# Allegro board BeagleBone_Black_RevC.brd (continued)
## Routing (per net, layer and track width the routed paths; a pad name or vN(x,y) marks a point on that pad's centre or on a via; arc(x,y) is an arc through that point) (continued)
DDR_DQM1: length 20.2
  TOP w0.121: U12.D3 61.5,28.76 60.01,28.76 59.44,28.19 57.78,28.19 57.66,28.32 57.66,28.57 57.78,28.7 59.31,28.7 59.44,28.83 59.44,29.08 59.31,29.21 57.78,29.21 57.66,29.34 57.66,29.59 57.78,29.72 59.31,29.72 59.44,29.84 59.44,30.1 59.31,30.23 56.77,30.23 56.64,30.1 56.64,29.34 56.52,29.21 52.12,29.21 U5.J2
DDR_DQS0: length 23.3
  TOP w0.095: U12.F3 61.62,26.77 61.54,26.69 61.54,26.44 61.62,26.37 62.22,26.37 62.29,26.44 62.29,26.73 62.37,26.8 62.6,26.8 62.67,26.73 62.67,26.32 62.75,26.24 62.93,26.24 63.22,26.53 63.22,30.75 61.69,32.28 61.69,32.99 62.01,33.31 62.99,33.31 63.12,33.43 63.12,33.66 62.99,33.78 54.62,33.78 53.76,32.91 52.62,32.91 U5.P1
DDR_DQS1: length 20.3
  TOP w0.095: U5.L1 53.45,30.41 v1(53.85,30.81)
  TOP w0.121: v1(65.5,29.57) U12.C7
  BOTTOM w0.095: v1(65.5,29.57) 65.54,29.57 65.61,29.64 65.61,29.9 65.54,29.97 63.64,29.97 63.35,30.26 63.35,30.85 63.64,31.14 63.91,31.14 64.14,31.37 64.14,31.75 62.86,33.03 54.76,33.03 54.38,32.65 54.38,32.42 54.76,32.04 54.76,31.66 54.47,31.37 53.75,31.37 53.62,31.24 53.62,31.04 v1(53.85,30.81)
DDR_DQSN0: length 23.3
  TOP w0.095: U12.G3 63.05,25.97 63.5,26.42 63.5,30.86 61.97,32.39 61.97,32.87 62.12,33.03 63.11,33.03 63.4,33.32 63.4,33.77 63.11,34.06 54.51,34.06 53.64,33.19 52.1,33.19 U5.P2
DDR_DQSN1: length 20.3
  TOP w0.095: v1(53.09,30.81) 52.12,30.81 U5.L2
  TOP w0.121: v1(65.5,30.37) U12.B7
  BOTTOM w0.095: v1(53.09,30.81) 53.34,31.06 53.34,31.36 53.63,31.65 54.36,31.65 54.48,31.78 54.48,31.93 54.1,32.31 54.1,32.77 54.64,33.31 62.97,33.31 64.41,31.87 64.41,31.25 64.02,30.86 63.75,30.86 63.63,30.73 63.63,30.38 63.75,30.25 65.39,30.25 v1(65.5,30.37)
DDR_ODT: length 24.1
  TOP w0.121: v1(57.91,23.88) 58.04,23.75 58.04,22.1 57.91,21.97 57.68,21.97 57.55,22.1 57.55,23.48 57.4,23.62 57.4,24.26 57.3,24.37 56.86,24.37 56.75,24.26 56.75,21.7 56.64,21.59 56.49,21.59 56.39,21.7 56.39,24.89 56.13,25.15 55.5,25.15 55.12,25.53 55.12,26.42 54.32,27.21 53.68,27.21 U5.G1 ; v1(59.9,23.16) U12.K1
  LYR3 w0.133: v1(57.91,23.88) 57.91,24.38 57.66,24.64 57.66,25.02 57.78,25.15 58.17,25.15 58.42,24.89 58.42,23.5 58.29,23.37 58.04,23.37 57.91,23.24 57.91,22.99 58.04,22.86 58.93,22.86 59.23,23.16 v1(59.9,23.16)
DDR_RASN: length 24
  TOP w0.121: U5.G4 v1(50.52,26.81) ; v1(61.5,23.96) U12.J3
  LYR3 w0.121: v1(50.52,26.81) 50.12,26.41 50.12,25.83 50.34,25.61 50.72,25.61 50.92,25.41 50.92,25.02 51.17,24.77 51.33,24.77
  LYR3 w0.133: 51.33,24.77 54.23,24.77 54.74,25.27 54.74,25.91 54.24,26.4 53.47,26.4 53.34,26.53 53.34,27.43 53.47,27.56 54.99,27.56 56.5,26.05 57.77,26.05 59.42,24.4 61.35,24.4 61.59,24.64 62.1,24.64 62.84,23.9 62.84,23.72 62.69,23.58 62.51,23.58 62.12,23.96 v1(61.5,23.96)
DDR_RESETN: length 20.7
  TOP w0.121: U5.G2 52.12,27.61 54.43,27.61 55.5,26.54 55.5,25.78 55.75,25.53 56.39,25.53 56.75,25.16 57.89,25.16 58.42,24.64 58.42,21.97 58.67,21.72 58.67,18.03 58.8,17.91 60.24,17.91 v1(60.7,18.36) U12.T2
  BOTTOM w0.121: v1(60.7,18.36) U12.T2 61.96,18.76 62.36,19.16 R97.2
DDR_VREF: length 26.3
  TOP w0.121: v1(59.9,25.57) U12.H1 ; v1(66.3,21.56) U12.M8 ; v1(50.52,28.41) U5.J4
  BOTTOM w0.121: v1(66.3,21.56) 65.17,21.56 64.77,21.96 C124.1 R100.1 64.01,23.62 63.82,23.81 63.18,23.81 62.99,24 C123.1 R98.2 ; v1(50.52,28.41) 50.92,28.01 54.03,28.01 54.88,27.17 C28.1 55.37,26.8 55.5,26.67 62.61,26.67 62.99,26.29 R98.2 ; R98.2 62.4,25.57 61.98,25.15 60.32,25.15 v1(59.9,25.57)
DDR_VTP: length 4.6
  TOP w0.254: v1(51.32,28.41) U5.J3
  BOTTOM w0.381: v1(51.32,28.41) R22.2
DDR_WEN: length 23.9
  TOP w0.121: v1(61.5,22.36) U12.L3 ; v1(55.37,17.53) 53.47,19.43 53.47,20.32 52.96,20.83 52.24,20.83 52.12,20.95 52.12,22.57 51.72,22.97 U5.B2
  LYR3 w0.133: v1(61.5,22.36) 61.87,22.73 62.48,22.73 63.5,21.72 63.5,20.95 63.12,20.57 63.12,17.27 62.23,16.38 56.77,16.38 55.63,17.52 55.38,17.52 v1(55.37,17.53)
DVI_+5V: length 21.8
  BOTTOM w0.203: 79.89,26.95 P6.19 79.59,26.95 79.37,27.17
  BOTTOM w0.381: 76.33,27.62 R146.1 75.21,26.99 ; 76.33,27.62 78.92,27.62 79.37,27.17 ; 76.33,27.62 R147.1
  BOTTOM w0.508: 75.21,26.99 74.55,26.32 74.55,25.15 73.28,23.88 73.28,22.35 71.75,20.83 71.75,14.61 RT1.2
EHRPWM1A: length 41.9
  TOP w0.121: v1(40.01,38.1) 40.26,38.1 41.72,36.64 41.72,35.61 U5.U14
  LYR4 w0.133: v1(40.01,38.1) 39.75,37.85 38.73,37.85 37.34,36.45 37.34,35.81 37.12,35.6 36.23,35.6 34.8,34.16 34.8,22.81 34.54,22.56 34.54,17.27 33.55,16.28 33.55,5.82 P9.14
EHRPWM1B: length 37.1
  TOP w0.121: v1(41.72,34.81) U5.T14
  LYR4 w0.133: v1(41.72,34.81) 41.22,35.31 39.75,35.31 38,33.55 36.6,33.55 36.32,33.27 36.32,24.51 36.49,24.35 36.49,19.34 35.56,18.41 35.56,10.79 37.47,8.89 P9.16
EHRPWM2A: length 16.8
  TOP w0.121: U5.U10 45.72,35.61 45.72,36.39 46.18,36.85 46.18,38.23 45.47,38.94 45.47,43.69 43.62,45.53 43.62,49.09 P8.19
EHRPWM2B: length 23.9
  TOP w0.121: v1(44.92,34.81) U5.T10
  LYR3 w0.133: P8.13 33.66,48.9 33.66,45.85 34.67,44.83 38.23,44.83 39.12,43.94 39.12,43.05 40.13,42.04 41.27,42.04 42.8,40.51 42.8,39.5 43.43,38.86 43.43,36.58 44.92,35.09 v1(44.92,34.81)
EMMC_RSTN: length 4.8
  TOP w0.203: U13.K5 v2(29.09,43.66)
  BOTTOM w0.121: R162.2 R111.2 29.21,44.57 29.09,44.45 v2(29.09,43.66)
EMMC_VCCI: length 1.9
  TOP w0.121: U13.C2 v2(32.35,44.91)
  BOTTOM w0.121: v2(32.35,44.91) 32.38,44.95 C125.1
ENZ_KALDO_1P8V: length 3.4
  TOP w0.121: U5.B4 v1(50.52,22.81)
  BOTTOM w0.121: R54.2 51.12,22.21 v1(50.52,22.81)
ETH_RESETN: length 7.4
  TOP w0.121: U14.19 25.83,34.24 26.65,35.05 v1(27.43,35.05)
  BOTTOM w0.121: 27.48,37.45 26.91,37.45 26.79,37.34 C174.1 R33.2 ; 27.48,37.45 U1.4 ; 27.48,37.45 27.3,37.28 27.3,36.22 27.43,36.1 v1(27.43,35.05)
ETH_RST_GPIO1_8: length 27.7
  TOP w0.121: U5.E18 38.18,25.61 37.59,25.02 35.69,25.02 33.62,22.95 33.62,22.82 v1(33.35,22.56)
  LYR4 w0.133: v1(33.35,22.56) 33.35,23.07 33.78,23.5 33.78,38.46 v1(33.66,38.59)
  BOTTOM w0.121: v1(33.66,38.59) 33.29,38.23 32.26,38.23 31.75,37.72 31.24,37.72 30.21,38.75 U1.1
ETH_TXD4: length 4.4
  TOP w0.121: v1(29.21,34.61) 26.7,34.61 26.33,34.24 U14.18
  BOTTOM w0.121: R145.1 v1(29.21,34.61)
GPIO0_7: length 48
  TOP w0.121: R50.1 36.32,18.29 v1(36.07,18.03)
  BOTTOM w0.121: P9.42 68.9,6.03 65.09,6.03 61.47,9.65 61.47,12.57 60.45,13.59 46.99,13.59 46.81,13.4 42.09,13.4 41.27,14.22 41.27,17.91 40.64,18.54 R51.1 40.13,19.18 39.12,20.19 36.7,20.19 36.47,19.96 36.47,19.45 36.07,19.05 v1(36.07,18.03)
GPIO0_7SRC: length 9.6
  TOP w0.121: R50.2 36.07,17.27 35.56,17.78 35.56,19.94 36.06,20.44 36.57,20.44 37.08,20.95 37.08,22.48 38.62,24.01 U5.C18
GPIO0_26: length 26.3
  TOP w0.121: v1(44.12,34.81) U5.T11
  LYR3 w0.133: v1(44.12,34.81) 44.12,35.38 43.05,36.45 43.05,38.73 42.42,39.37 42.42,40.39 41.15,41.66 40.01,41.66 38.61,43.05 38.61,43.81 37.97,44.45 34.54,44.45 33.27,45.72 33.27,49.15 33.66,49.53 33.66,51.44 P8.14
GPIO0_27: length 16.6
  TOP w0.121: P8.17 41.27,48.9 41.27,48.39 43.05,46.61 43.05,45.09 43.43,44.7 43.43,36.32 43.32,36.21 43.32,35.61 U5.U12
GPIO1_12: length 26.5
  TOP w0.121: v1(43.32,34.81) U5.T12
  LYR3 w0.133: P8.12 31.24,51.56 31.24,46.61 34.16,43.69 37.47,43.69 37.85,43.31 37.85,42.8 39.75,40.89 40.89,40.89 41.66,40.13 41.66,38.99 42.29,38.35 42.29,36.2 43.32,35.17 v1(43.32,34.81)
GPIO1_13: length 24.7
  TOP w0.121: v1(43.32,34.01) U5.R12
  LYR3 w0.121: v1(43.32,34.01) 43.72,34.41 43.72,35.27
  LYR3 w0.133: 43.72,35.27 42.67,36.32 42.67,38.61 42.07,39.21 42.07,40.23 41.02,41.27 39.88,41.27 38.23,42.93 38.23,43.56 37.72,44.07 34.42,44.07 31.71,46.78 31.71,49.49 P8.11
GPIO1_14: length 19.8
  TOP w0.121: U5.V13 42.92,36.32 43.18,36.58 43.18,44.45 42.04,45.59 42.04,47.24 40.77,48.51 39.76,48.51 38.73,49.53 38.73,51.44 P8.16
GPIO1_15: length 18.3
  TOP w0.121: P8.15 39.5,48.13 40.77,48.13 41.78,47.12 41.78,45.34 42.92,44.2 42.92,36.83 42.52,36.43 42.52,35.61 U5.U13
GPIO1_16: length 52.9
  LYR4 w0.133: v1(37.15,43.18) 35.5,41.53 34.42,41.53 32.91,40.02 32.91,37.83 33.15,37.59 33.15,36.88 32.51,36.24 32.51,26.24 32.89,25.86 32.89,25.15 33.3,24.74 33.3,23.78 32.12,22.61 31.63,22.61 31.24,22.22 31.24,19.68 31.75,19.18 31.75,7.37 31.24,6.86 31.24,4.06 32.26,3.05 36.32,3.05 P9.15
  BOTTOM w0.121: R160.2 R161.2 v1(37.15,43.18)
GPIO1_17: length 53.5
  TOP w0.121: v1(40.89,38.1) 42.12,36.87 U5.V14
  LYR4 w0.133: v1(35.31,6.48) 34.92,6.86 34.92,7.29 34.8,7.41 34.8,22.48 35.05,22.73 35.05,34.04 36.38,35.36 37.27,35.36 37.59,35.69 37.59,36.2 38.99,37.59 40.39,37.59 v1(40.89,38.1)
  BOTTOM w0.121: P9.23 46.35,3.17 46.35,4.83 45.59,5.59 36.2,5.59 v1(35.31,6.48)
GPIO1_28: length 37.4
  TOP w0.121: v1(36.83,36) 37.62,35.21 U5.U18
  LYR4 w0.133: v1(36.83,36) 36.42,36.41 35.14,36.41 34.29,35.56 34.29,23.11 34.04,22.86 34.04,17.78 32.66,16.41 32.66,5.87 32.38,5.59 P9.12
GPIO1_29: length 18
  TOP w0.121: P8.26 48.9,51.44 48.9,49.28 49.66,48.51 49.66,45.34 48.77,44.45 48.77,38.61 48.52,38.36 U5.V6
GPIO2_1: length 18.2
  TOP w0.121: U5.V12 43.72,44.96 43.31,45.37 43.31,46.74 41.66,48.39 41.66,49.28 41.27,49.66 41.27,51.44 P8.18
GPIO3_18: length 5.9
  TOP w0.121: U5.B12 43.32,22.81 43.32,22.23 42.6,21.52 42.09,21.52 40.77,20.19 v1(40.01,20.19)
  BOTTOM w0.121: v1(40.01,20.19) R51.2
GPIO3_19: length 28.5
  TOP w0.121: v1(42.52,23.61) U5.C13
  LYR4 w0.133: P9.27 51.56,3.05 49.53,3.05 48.77,3.81 48.77,8 42.93,13.84 42.93,14.61 43.31,14.99 43.31,20.07 41.85,21.52 41.85,22.94 v1(42.52,23.61)
GPIO3_20: length 5.9
  TOP w0.121: U5.D13 v1(42.52,25.21)
  BOTTOM w0.121: v1(42.52,25.21) 42.12,24.81 42.12,21.38 42.55,20.95 R20.2
GPIO3_21: length 68.2
  TOP w0.121: P9.25 48.9,3.17 48.9,4.95 48.01,5.84 44.7,5.84 44.2,6.35 41.78,6.35 39.37,8.76 39.37,11.14 39.66,11.43 40.13,11.43 40.39,11.68 40.39,15.24 38.99,16.64 v1(38.99,19.68) 38.99,20.07 39.75,20.83 40.89,20.83 41.97,21.9 41.97,22.26 U5.A14
  LYR3 w0.133: v1(38.99,19.68) 38.28,20.4 35.1,20.4 33.59,21.91 v1(31.76,21.91)
  LYR4 w0.133: v1(31.76,21.91) 33.53,23.68 33.53,37.71 33.15,38.1 33.15,39.24 33.4,39.5 38.23,39.5 39.12,40.39 40.64,40.39 v1(41.15,39.88)
  BOTTOM w0.121: R167.2 40.96,40.07 v1(41.15,39.88)
GRN_C: length 2
  BOTTOM w0.121: R132.2 5.21,32.26 4.88,32.59 P5.10
GRNA: length 32.3
  TOP w0.121: v1(24.45,27.69) 24.33,27.8 U14.3
  LYR3 w0.133: v1(24.45,27.69) 23.56,28.57 22.48,28.57 21.59,27.69 20.95,27.69 17.65,24.38 14.73,24.38 12.19,26.92 7.11,26.92 3.35,30.68 P5.9
HDMI_1V8: length 22.4
  TOP w0.254: v1(65.66,34.8) 65.75,34.89 U11.29 ; U11.48 68.52,43.76 v1(68.58,43.81) ; U11.5 58.45,41.76 v1(58.42,41.78) ; v1(64.64,45.21) 64.64,45.19 64.25,44.79 U11.55 ; U11.14 58.5,37.25 v1(58.42,37.34) ; U11.41 68.46,40.25 v1(68.58,40.13) ; U11.35 68.45,37.25 v1(68.58,37.38) 68.58,37.5 68.33,37.76 U11.36 ; U11.47 68.58,43.25 ; U11.46 v1(68.58,42.76)
  TOP w0.381: v1(68.58,43.81) v1(68.58,42.76)
  BOTTOM w0.381: C146.1 64.64,44.32 ; 64.64,44.32 C148.1 ; 64.64,44.32 v1(64.64,45.21) ; v1(54.48,38.1) 55.56,38.1 FB5.1 55.57,37.47 v1(54.48,37.47) ; C150.1 68.33,40.39 v1(68.58,40.13) ; v1(68.58,37.38) 67.29,37.38 66.67,36.77 C151.1 ; v1(58.42,37.34) 58.67,37.34 59.05,36.96 C145.1 ; C144.1 58.67,41.15 58.42,41.4 v1(58.42,41.78) ; v1(65.66,34.8) 65.41,35.05 C147.1 ; v1(68.58,42.76) 68.58,43.31 ; 68.58,43.31 v1(68.58,43.81) ; 68.58,43.31 67.94,43.31
HDMI_CEC: length 20.5
  TOP w0.121: U11.30 66.25,35.1 66.8,34.54 67.44,34.54 68.07,33.91 69.22,33.91 72.15,30.97 D8.1 73.93,30.97 74.93,29.97 74.93,26.16 v1(75.18,25.91)
  BOTTOM w0.121: 79.89,26.15 P6.15 79.32,26.15 79.07,26.4 75.68,26.4 v1(75.18,25.91)
HDMI_CEC_D: length 1.5
  TOP w0.121: R166.1 D8.2
HDMI_DSCL: length 18.9
  TOP w0.121: U11.33 68.34,36.25 72.08,32.51 74.93,32.51 76.45,30.99 76.45,27.69 77.15,26.99 v1(78.23,26.99)
  BOTTOM w0.121: 79.89,26.55 P6.17 79.27,26.55 79.15,26.67 78.55,26.67 v1(78.23,26.99) 77.34,26.99
HDMI_DSDA: length 19.1
  TOP w0.121: U11.32 68.49,35.65 72.01,32.13 74.8,32.13 75.95,30.99 v1(75.95,28.96)
  BOTTOM w0.121: P6.18 81.11,26.95 81.01,27.05 80.59,27.05 79.38,28.26 77.34,28.26 77.34,28.7 77.09,28.96 v1(75.95,28.96)
HDMI_HPD: length 22.6
  TOP w0.121: v1(78.99,23.35) 79.69,24.04 79.69,26.04 79.18,26.54 76.58,26.54 75.44,27.69 75.44,30.23 73.91,31.75 71.95,31.75 69.41,34.29 68.2,34.29 67.56,34.92 66.93,34.92 66.75,35.1 U11.31
  BOTTOM w0.121: v1(78.99,23.35) P6.1 79.89,23.35
HDMI_INT: length 40.4
  TOP w0.121: U11.50 66.75,45.16 v1(66.8,45.21) ; U5.U16 40.12,35.61 39.56,35.61 39.32,35.85 39.32,36.24 38.99,36.58 38.58,36.58 v1(37.57,37.58)
  LYR4 w0.133: v1(37.57,37.58) 39.46,39.47 42.01,39.47 47.62,45.09 47.88,45.09 48.13,45.34 48.13,46.1 49.26,47.22 64.79,47.22 v1(66.8,45.21)
  BOTTOM w0.121: R158.2 37.57,38.4 v1(37.57,37.58)
HDMI_SWING: length 1.5
  TOP w0.121: v1(68.58,36.58) 68.4,36.76 U11.34
  BOTTOM w0.121: v1(68.58,36.58) 68.45,36.7 R148.1
HDMI_TX0+: length 32
  TOP w0.095: D6.2 74.81,35.43 v1(74.93,35.31) 75.32,35.69 75.32,36.44 74.9,36.86 72.76,36.86 71.77,37.85 71.12,37.85 69.22,39.74 67.86,39.74 U11.40
  LYR4 w0.102: v1(74.93,35.31) 75.14,35.31 78.61,31.83 78.61,31.67 78.49,31.55 77.34,31.55 77.04,31.24 77.04,30.79 77.34,30.48 78.49,30.48 78.61,30.35 78.61,30.15 78.49,30.02 77.34,30.02 77.04,29.72 77.04,29.26 77.34,28.96 78.49,28.96 78.61,28.83 78.61,28.63 78.49,28.5 77.72,28.5 77.09,27.86 77.09,26.62 77.47,26.24 v1(77.47,25.91)
  BOTTOM w0.095: 79.89,24.95 P6.9 78.65,24.95 77.91,25.68 77.7,25.68 v1(77.47,25.91)
HDMI_TX0-: length 32.1
  TOP w0.095: U11.39 68.21,39.25 68.42,39.47 69.11,39.47 71,37.57 71.65,37.57 72.64,36.58 74.79,36.58 74.93,36.43 v1(74.93,36.07) 74.79,35.92 D6.1
  LYR4 w0.102: v1(78.23,25.91) 77.39,26.75 77.39,27.74 77.85,28.19 78.61,28.19 78.92,28.5 78.92,28.96 78.61,29.26 77.47,29.26 77.34,29.39 77.34,29.59 77.47,29.72 78.61,29.72 78.92,30.02 78.92,30.48 78.61,30.78 77.47,30.78 77.34,30.91 77.34,31.11 77.47,31.24 78.62,31.24 78.92,31.54 78.92,31.96 75.32,35.56 75.32,36.54 75.21,36.65 75.04,36.65 74.93,36.54 v1(74.93,36.07)
  BOTTOM w0.095: 79.89,25.35 P6.11 79.38,25.35 79.25,25.23 78.76,25.23 78.22,25.76 78.22,25.9 v1(78.23,25.91)
HDMI_TX1+: length 32.1
  TOP w0.095: U11.43 68.3,41.25 68.52,41.03 69.22,41.03 71.64,38.61 71.9,38.61 72.76,37.74 74.81,37.74 74.93,37.86 v1(74.93,38.23) 74.79,38.37 D7.5
  LYR4 w0.102: v1(74.93,38.23) 74.93,37.19 75.03,37.08 75.21,37.08 75.31,37.19 75.31,38.56 75.44,38.68 75.74,38.68 76.71,37.72 76.71,35.38 79.71,32.39 79.71,27.23 82.32,24.61 82.32,24.45 82.22,24.35 v1(82.04,24.35)
  BOTTOM w0.095: P6.6 v1(82.04,24.35)
HDMI_TX1-: length 32.1
  TOP w0.095: U11.42 69.1,40.76 71.53,38.33 71.78,38.33 72.64,37.47 74.93,37.47 75.32,37.85 75.32,38.6 v1(74.93,38.99) 74.81,38.87 D7.4
  LYR4 w0.102: v1(74.93,38.99) 75.87,38.99 77.01,37.85 77.01,35.51 80.01,32.51 80.01,27.36 82.8,24.56 v1(82.8,24.35)
  BOTTOM w0.095: P6.8 82.4,24.75 v1(82.8,24.35)
HDMI_TX2+: length 32.1
  TOP w0.095: v1(72.14,39.88) 72.26,40.01 73.32,40.01 D7.2 74.48,39.87 74.75,40.13 74.75,40.82 74.14,41.43 70.59,41.43 69.98,42.03 68.45,42.03 68.23,42.25 U11.45
  LYR4 w0.102: v1(72.14,39.88) 72.34,40.08 72.52,40.08 74.04,38.56 74.04,28.91 76.15,26.8 76.15,26.11 v1(75.95,25.91)
  BOTTOM w0.095: 79.89,23.75 P6.3 79.28,23.75 79.22,23.81 78.56,23.81 77.37,24.99 76.86,24.99 v1(75.95,25.91)
HDMI_TX2-: length 32.1
  TOP w0.095: v1(72.14,40.64) 72.14,40.51 72.28,40.37 D7.1 74.4,40.37 74.47,40.44 74.47,40.71 74.03,41.15 70.47,41.15 69.86,41.76 U11.44
  LYR4 w0.102: v1(76.71,25.91) 76.45,26.16 76.45,26.92 76.15,27.23 76.15,27.37 76.2,27.42 76.2,27.56 76.07,27.69 75.9,27.69 75.86,27.66 75.72,27.66 75.58,27.8 75.58,27.94 75.69,28.05 75.69,28.2 75.54,28.34 75.4,28.34 75.29,28.23 75.15,28.23 75,28.38 75,28.52 75.11,28.63 75.11,28.77 74.97,28.92 74.83,28.92 74.71,28.81 74.57,28.81 74.35,29.03 74.35,38.68 72.64,40.39 72.39,40.39 v1(72.14,40.64)
  BOTTOM w0.095: v1(76.71,25.91) 76.71,25.54 76.98,25.27 77.48,25.27 78.67,24.09 79.22,24.09 79.28,24.15 P6.5 79.89,24.15
HDMI_TXC+: length 32
  TOP w0.095: U11.38 68.05,38.76 68.22,38.59 68.99,38.59 70,37.58 70,35.79 71.5,34.29 72.32,34.29 72.46,34.42 D6.4 74.29,34.42 74.51,34.2 75.03,34.2 76.6,32.64 78.74,32.64 79.12,32.26 79.12,31.62 78.71,31.22 77.34,31.22 77.22,31.09 77.22,30.61 77.34,30.48 78.49,30.48 78.87,30.1 78.87,29.34 78.61,29.08 77.34,29.08 77.22,28.96 77.22,28.07 77.34,27.94 79.14,27.94 80.41,26.67 82.08,26.67 v1(82.8,25.95)
  BOTTOM w0.095: P6.12 82.4,25.55 v1(82.8,25.95)
HDMI_TXC-: length 32
  TOP w0.095: v1(82.04,25.95) 82.04,25.35 81.92,25.22 81.66,25.22 81.53,25.35 81.53,26.26 81.41,26.39 80.29,26.39 79.02,27.66 77.23,27.66 76.94,27.95 76.94,29.07 77.23,29.36 78.49,29.36 78.59,29.46 78.59,29.98 78.37,30.2 77.23,30.2 76.94,30.49 76.94,31.21 77.23,31.5 78.6,31.5 78.84,31.74 78.84,32.14 78.62,32.36 76.48,32.36 74.91,33.93 D6.5 73.37,34.01 71.39,34.01 69.72,35.67 69.72,37.47 69.45,37.73 69.32,37.73 69.2,37.62 69.06,37.62 68.93,37.75 68.93,37.88 69.05,38 69.05,38.14 68.88,38.31 67.9,38.31 U11.37
  BOTTOM w0.095: P6.14 v1(82.04,25.95)
HDMICLK_DISN: length 9.7
  TOP w0.121: U5.V17 39.72,36.23 37.47,38.48 v1(36.07,38.48) ; Y4.1 v1(39.5,39.88)
  LYR4 w0.133: v1(39.5,39.88) 39.11,39.88 38.35,39.12 36.7,39.12 v1(36.07,38.48)
I2C0_SCL: length 85.2
  TOP w0.121: v1(26.92,19.56) 26.04,20.45 R3.2 ; U11.52 65.75,44.99 v1(65.53,45.21) ; v1(40.12,23.61) U5.C16 ; v1(26.92,14.03) 26.72,14.24 U2.28
  LYR3 w0.133: v1(46.28,45.01) 47.17,45.01 v1(47.73,44.45)
  LYR4 w0.133: v1(46.28,45.01) 45.34,44.07 37.34,44.07 35.18,41.91 34.29,41.91 32.68,40.3 32.68,37.68 32.89,37.47 32.89,36.96 32.26,36.32 32.26,26.16 32.61,25.81 32.61,24.61 32.38,24.38 32.38,23.75 v1(31.75,23.11) ; v1(65.53,45.21) 65.53,45.72 64.26,46.99 49.91,46.99 49.4,46.48 49.4,44.96 48.9,44.45 v1(47.73,44.45) ; v1(26.92,14.03) 27.56,14.67 27.56,18.92 v1(26.92,19.56)
  BOTTOM w0.121: v1(26.92,19.56) 28.19,19.56 28.98,20.34 28.98,21.74 30.1,22.86 U7.1 31.5,22.86 v1(31.75,23.11) 34.36,23.11 34.87,22.61 36.17,22.61 37.67,21.1 39.14,21.1 39.72,21.69 39.72,23.21 v1(40.12,23.61)
I2C0_SDA: length 87.5
  TOP w0.121: U5.C17 39.32,23.61 38.72,23.61 37.34,22.23 37.34,20.83 36.58,20.07 36.45,20.07 v1(36.07,19.68) ; v1(66.17,45.21) 66.25,45.13 U11.51 ; R4.2 v1(26.99,20.57) ; v1(26.92,13.4) 26.48,13.84 U2.27
  LYR3 w0.133: v1(26.99,20.57) 27.62,21.21 33.27,21.21 34.8,19.68 v1(36.07,19.68)
  LYR4 w0.133: v1(26.99,20.57) 27.81,19.75 27.81,14.29 v1(26.92,13.4) ; v1(66.17,45.21) 65.76,44.81 65.3,44.81 65.13,44.98 65.13,45.49 63.88,46.74 50.16,46.74 49.66,46.23 49.66,43.81 48.9,43.05 46.23,43.05 42.16,38.99 42.16,37.72 40.26,35.81 39.62,35.81 37.72,33.91 36.45,33.91 36.07,33.53 36.07,24.38 36.2,24.25 36.2,22.79 35.56,22.15 35.56,20.19 v1(36.07,19.68)
  BOTTOM w0.121: v1(26.99,20.57) 26.42,20 26.42,19.3 26.67,19.05 28.32,19.05 29.34,20.07 30.48,20.07 30.82,20.41 U7.3
I2C1_SCL: length 22.2
  TOP w0.121: U5.A16 v1(40.12,22.01)
  LYR4 w0.133: v1(40.12,22.01) 40.12,21.6 41.4,20.32 41.4,13.34 41.91,12.83 41.91,9.4 41.27,8.76 41.27,3.17 P9.17
I2C1_SDA: length 20.6
  TOP w0.121: U5.B16 v1(40.12,22.81)
  LYR4 w0.133: P9.18 41.02,5.46 41.02,9.02 41.66,9.65 41.66,12.57 41.15,13.08 41.15,20.07 39.71,21.5 39.71,22.4 v1(40.12,22.81)
I2C2_SCL: length 31.8
  TOP w0.121: U5.D17 39.32,24.41 38.51,24.41 37.72,23.62 36.06,23.62 36.01,23.57 v1(35.54,23.57) ; P9.19 41.27,3.17 41.27,4.83 40.51,5.59 36.96,5.59 v1(36.07,6.48)
  LYR4 w0.133: v1(35.54,23.57) 35.54,22.84 35.03,22.33 35.03,7.51 v1(36.07,6.48)
I2C2_SDA: length 28.9
  TOP w0.121: P9.20 42.16,4.45 40.64,5.97 37.34,5.97 v1(36.83,6.48) ; v1(35.72,24.1) 36.09,24.1 36.32,23.88 37.47,23.88 38.4,24.81 U5.D18
  LYR4 w0.133: v1(36.83,6.48) 36.83,9.02 35.31,10.54 35.31,22.23 35.97,22.89 35.97,23.85 v1(35.72,24.1)
JTAG_EMU0: length 25.6
  TOP w0.121: v1(41.72,23.61) U5.C14 ; v1(34.29,11.75) 34.42,11.87 R23.2
  LYR3 w0.133: v1(34.29,14.92) 34.86,15.49 38.35,15.49 38.61,15.75 v1(42.42,15.75)
  LYR4 w0.133: v1(34.29,14.92) 33.88,14.52 33.88,12.15 v1(34.29,11.75) ; v1(42.42,15.75) 42.93,16.26 42.93,20.07 41.59,21.4 41.59,23.48 v1(41.72,23.61)
  BOTTOM w0.121: P2.13 v1(34.29,14.92)
JTAG_EMU1: length 15.5
  TOP w0.121: R24.2 36.26,15.11 v1(36.07,14.92) ; v1(39.88,14.92) 39.88,15.24 38.59,16.53 38.59,20.05 39.75,21.21 40.77,21.21 41.72,22.16 41.72,22.81 U5.B14
  BOTTOM w0.121: v1(39.88,14.92) P2.14 v1(36.07,14.92)
JTAG_TCK: length 24.5
  TOP w0.121: v1(41.15,11.94) 40.89,12.19 40.89,15.37 40.39,15.88 40.39,19.3 42.35,21.27 42.73,21.27 43.4,21.94 43.4,21.94 43.72,22.26 U5.A12
  LYR3 w0.133: v1(34.29,12.38) 34.73,11.94 36.32,11.94 36.83,11.43 40.64,11.43 v1(41.15,11.94)
  BOTTOM w0.121: P2.11 34.1,13.65 34.29,13.46 v1(34.29,12.38) P2.9
JTAG_TDI: length 24.1
  TOP w0.121: U5.B11 44.12,22.81 44.12,22.17 42.87,20.92 42.51,20.92 40.8,19.21 40.8,16.06 41.27,15.59 41.27,13.08 41.66,12.7 41.66,11.68 41.4,11.43 41.02,11.43 40.51,10.92 v1(39.88,10.92)
  BOTTOM w0.121: v1(39.88,10.92) 39.88,10.79 39.56,10.48 36.26,10.48 34.35,8.57 P2.3
JTAG_TDO: length 24.3
  TOP w0.121: v1(41.15,10.92) 41.4,10.92 42.04,11.56 42.04,12.83 41.66,13.21 41.66,15.81 41.15,16.32 41.15,19.05 42.54,20.44 42.54,20.45 43.56,20.45 44.2,21.08 44.2,21.72 44.52,22.04 U5.A11
  LYR3 w0.133: v1(41.15,10.92) 40.64,10.41 40.64,10.16 40.13,9.65 36.32,9.65 34.86,11.11 v1(34.29,11.11)
  BOTTOM w0.121: P2.7 v1(34.29,11.11)
JTAG_TMS: length 29.2
  TOP w0.121: v1(45.09,15.75) 44.64,15.3 44.64,13.53 44.2,13.08 v1(44.2,8.89) ; U5.C11 v1(44.12,23.61)
  LYR4 w0.133: v1(44.12,23.61) 45.09,22.64 45.09,19.68 44.58,19.18 44.58,16.26 v1(45.09,15.75)
  BOTTOM w0.121: P2.1 34.86,7.3 35.5,7.94 40.2,7.94 41.66,9.4 43.69,9.4 v1(44.2,8.89)
JTAG_TRSTN: length 25.6
  TOP w0.121: v1(36.07,7.3) 36.64,7.3 36.83,7.49 R25.1 ; v1(42.55,8.89) 42.55,12.83 41.91,13.46 41.91,16 41.4,16.51 41.4,18.92 42.67,20.19 43.69,20.19 44.45,20.95 44.45,21.59 44.92,22.06 44.92,22.81 U5.B10
  BOTTOM w0.121: v1(36.07,7.3) P2.2 40.07,7.3 41.66,8.89 v1(42.55,8.89)
LCD_DATA0: length 40.4
  TOP w0.121: R95.1 v1(71.75,48.26) ; C173.1 P8.45 ; U5.R1 53.3,33.61 54.36,34.67 57.02,34.67 v1(57.15,34.8) 57.91,35.56 57.91,35.97 58.7,36.76 U11.15
  LYR3 w0.133: v1(57.15,34.8) 57.91,35.56 57.91,35.81 58.29,36.2 58.67,36.2 59.94,37.47 65.79,37.47 66.42,38.1 66.42,39.62 67.94,41.15 68.45,41.15 71.25,43.94 71.25,47.12 71.75,47.62 v1(71.75,48.26)
  BOTTOM w0.121: P8.45 74.3,48.9 72.39,48.9 v1(71.75,48.26) R95.1
LCD_DATA1: length 47.3
  TOP w0.121: P8.46 74.3,51.44 72.52,51.44 72.01,50.93 72.01,49.47 v1(70.8,48.26) R94.1 ; U5.R2 51.72,33.62 52.11,34.01 53.19,34.01 54.23,35.05 56.64,35.05 v1(57.15,35.56) 57.91,36.32 57.91,37.47 58.2,37.76 U11.13
  LYR3 w0.133: v1(70.8,48.26) 70.8,47.56 70.36,47.12 70.36,43.43 68.45,41.53 67.82,41.53 66.04,39.75 66.04,38.99 65.79,38.73 59.82,38.73 59.18,38.1 59.18,37.21 58.55,36.58 58.17,36.58 v1(57.15,35.56)
  BOTTOM w0.121: P8.46 76.58,51.69 76.58,49.15 75.56,48.13 C171.1 ; v1(70.8,48.26) R94.1
LCD_DATA2: length 39.8
  TOP w0.121: P8.43 73.66,49.53 R75.1 ; v1(51.32,34.01) U5.R3 ; U11.12 58.45,38.25 v1(58.42,38.23) ; R93.1 v1(69.85,48.26)
  LYR3 w0.133: v1(69.85,48.26) 69.85,47.62 69.34,47.12 69.34,42.8 68.58,42.04 67.69,42.04 65.66,40.01 60.33,40.01 59.05,38.73 58.93,38.73 v1(58.42,38.23)
  BOTTOM w0.121: P8.43 71.75,48.9 70.48,48.9 v1(69.85,48.26) R93.1 ; v1(51.32,34.01) 51.79,34.01 53.47,35.69 53.47,38.1 C172.1 56.77,39.88 v1(58.42,38.23)
LCD_DATA3: length 44.2
  TOP w0.121: P8.44 71.5,51.18 71.5,49.59 70.8,48.9 69.53,48.9 v1(68.9,48.26) R92.1 ; v1(50.52,34.01) U5.R4 ; U11.11 58.53,38.76 v1(58.42,38.86)
  LYR3 w0.133: v1(58.42,38.86) 60.83,41.27 65.91,41.27 67.82,43.18 68.71,43.18 69.09,43.56 69.09,44.83 68.33,45.59 68.33,46.74 68.9,47.31 v1(68.9,48.26)
  BOTTOM w0.121: v1(68.9,48.26) R92.1 ; v1(58.42,38.86) 56.64,40.64 56.64,41.15 55.63,42.16 53.72,42.16 53.47,41.91 53.47,40.39 C170.1 53.21,39.12 53.21,36.14 51.49,34.41 50.92,34.41 v1(50.52,34.01)
LCD_DATA4: length 32
  TOP w0.121: U5.T1 53.08,34.41 53.85,35.18 53.85,36.2 55.5,37.85 C169.1 56.9,37.85 v1(57.15,38.1) 57.15,38.61 57.85,39.31 58.62,39.31 58.67,39.25 U11.10 ; R91.1 v1(67.94,48.26)
  LYR3 w0.133: v1(67.94,48.26) 67.94,47.76 68.08,47.62 68.08,44.46 66.04,42.42 61.21,42.42 57.15,38.35 v1(57.15,38.1)
  BOTTOM w0.121: P8.41 69.22,48.9 68.58,48.9 v1(67.94,48.26) R91.1
LCD_DATA5: length 37.2
  TOP w0.121: R90.1 v1(66.99,48.26) 67.63,48.9 68.26,48.9 69.22,49.85 69.22,51.44 P8.42 ; U11.7 58.54,40.76 57.66,39.88 C163.1 v1(56.52,39.12) 56.01,38.61 54.36,38.61 53.59,37.85 53.59,35.43 52.97,34.81 52.12,34.81 U5.T2
  LYR3 w0.133: v1(56.52,39.12) 57.4,39.12 61.21,42.93 66.04,42.93 67.84,44.73 67.84,46.96 66.99,47.82 v1(66.99,48.26)
  BOTTOM w0.121: v1(66.99,48.26) R90.1
LCD_DATA6: length 34.1
  TOP w0.121: v1(51.32,34.81) U5.T3 ; U11.6 58.27,41.25 v1(57.66,40.64) ; R89.1 v1(66.04,48.26)
  LYR3 w0.133: v1(57.66,40.64) 58.42,40.64 60.96,43.18 63.88,43.18 65.09,44.39 65.09,47.31 v1(66.04,48.26)
  BOTTOM w0.121: v1(51.32,34.81) 52.07,35.56 52.07,39.24 C162.1 53.21,40.39 53.21,42.67 53.72,43.18 55.12,43.18 v1(57.66,40.64) ; R89.1 v1(66.04,48.26) P8.39
LCD_DATA7: length 43.4
  TOP w0.121: v1(57.66,43.18) 58.08,42.76 U11.3 ; v1(50.52,34.81) U5.T4 ; R88.1 v1(65.09,48.26) 66.67,49.85 66.67,51.44 P8.40
  LYR3 w0.133: v1(57.66,43.18) 57.02,43.81 57.02,48.51 57.53,49.02 58.17,49.02 58.93,49.78 58.93,50.67 59.82,51.56 66.8,51.56 P8.40
  BOTTOM w0.121: v1(57.66,43.18) 57.4,43.43 52.7,43.43 50.93,41.66 50.93,40.39 C161.1 50.93,39.37 50.93,38.48 51.18,38.23 51.18,35.47 v1(50.52,34.81) ; v1(65.09,48.26) R88.1
LCD_DATA8: length 31.9
  TOP w0.121: U11.2 58.49,43.25 v1(58.42,43.18) 57.91,43.69 57.15,43.69 55.24,41.78 C160.1 54.74,40.39 54.74,39.37 53.34,37.97 53.34,35.69 52.86,35.21 U5.U1 ; P8.37 64.14,48.9 v1(64.14,48.26) R87.1
  LYR3 w0.133: v1(58.42,43.18) 57.91,43.69 57.91,48.39 59.18,49.66 59.18,50.55 59.94,51.31 64.26,51.31 P8.37
  BOTTOM w0.121: v1(64.14,48.26) R87.1
LCD_DATA9: length 30.2
  TOP w0.121: U5.U2 51.96,35.21 52.36,35.61 52.75,35.61 53.09,35.94 53.09,38.1 53.98,38.99 C157.1 54.48,40.39 54.48,41.53 56.9,43.94 v1(58.42,43.94) 58.61,43.76 U11.1 ; P8.38 64.14,51.44 64.14,49.85 63.18,48.9 v1(63.18,48.26) R86.1
  LYR3 w0.133: v1(63.18,48.26) 63.18,48.32 62.36,49.15 59.56,49.15 58.93,48.51 58.93,44.45 v1(58.42,43.94)
  BOTTOM w0.121: v1(63.18,48.26) R86.1
LCD_DATA10: length 30
  TOP w0.121: v1(60.33,45.72) 59.75,45.14 U11.64 56.67,44.36 55.75,43.43 C156.1 55.24,42.8 54.61,42.16 53.72,42.16 53.47,41.91 53.47,38.86 52.07,37.47 52.07,36.22 52.12,36.17 52.12,35.85 51.88,35.61 51.32,35.61 U5.U3 ; P8.36 61.59,51.44 61.59,49.85 62.23,49.21 v1(62.23,48.26) R85.1
  LYR3 w0.133: v1(62.23,48.26) 61.59,48.9 61.01,48.9 61.01,48.9 60.2,48.9 59.82,48.51 59.82,47.88 60.33,47.37 v1(60.33,45.72)
  BOTTOM w0.121: v1(62.23,48.26) R85.1
LCD_DATA11: length 32.4
  TOP w0.121: U11.60 61.75,44.93 v1(61.47,45.21) ; C168.1 v1(52.7,42.67) 51.94,41.91 51.94,38.48 50.52,37.06 50.52,35.61 U5.U4 ; P8.34 59.05,51.44 59.05,49.53 59.37,49.21 v1(59.37,48.26) R84.1
  LYR3 w0.133: v1(52.7,42.67) 53.21,43.18 56.9,43.18 57.4,42.67 59.82,42.67 61.47,44.32 v1(61.47,45.21) 60.07,45.21 59.82,45.47 59.82,47.12 59.37,47.56 v1(59.37,48.26)
  BOTTOM w0.121: v1(59.37,48.26) R84.1
LCD_DATA12: length 26.9
  TOP w0.121: v1(56.13,44.7) 55.63,45.21 54.23,45.21 53.98,44.96 C167.1 53.47,43.94 53.47,42.29 53.21,42.04 53.21,38.99 51.72,37.5 U5.V2 ; v1(62.1,45.21) 62.25,45.06 U11.59 ; R83.1 v1(61.28,48.26)
  LYR3 w0.133: v1(61.28,48.26) 61.28,46.04 v1(62.1,45.21)
  BOTTOM w0.121: P8.35 61.28,48.58 v1(61.28,48.26) R83.1 ; v1(62.1,45.21) 61.59,44.7 v1(56.13,44.7)
LCD_DATA13: length 30.4
  TOP w0.121: v1(55.24,45.72) 54.1,45.72 53.21,44.83 53.21,42.55 52.83,42.16 52.58,42.16 52.2,41.78 52.2,40.39 C166.1 52.7,38.86 50.92,37.08 U5.V3 ; U11.58 62.75,45.2 v1(62.74,45.21) ; R82.1 v1(60.33,48.26)
  LYR3 w0.133: v1(60.33,48.26) 60.73,48.66 61.1,48.66 61.11,48.67 61.45,48.67 61.72,48.39 61.72,46.23 v1(62.74,45.21)
  LYR4 w0.133: v1(62.74,45.21) 61.72,46.23 55.75,46.23 v1(55.24,45.72)
  BOTTOM w0.121: P8.33 v1(60.33,48.26) R82.1
LCD_DATA14: length 42
  TOP w0.121: v1(63.37,45.21) 63.25,45.05 U11.57 ; R81.1 v1(57.47,48.26) 56.96,48.77 55.75,48.77 55.24,48.26 C165.1 52.96,47.5 51.94,46.48 51.94,42.8 50.96,41.82 50.96,37.88 50.12,37.04 U5.V4
  LYR4 w0.133: v1(57.47,48.26) 58.1,48.9 66.17,48.9 66.55,48.51 66.55,47.75 68.08,46.22 68.08,44.84 67.44,44.2 64.39,44.2 v1(63.37,45.21)
  BOTTOM w0.121: P8.31 57.78,49.21 57.47,48.9 v1(57.47,48.26) R81.1
LCD_DATA15: length 46.8
  TOP w0.121: U11.56 63.75,44.95 v1(64.01,45.21) ; v1(49.72,34.81) U5.T5 ; R80.1 v1(58.42,48.26) 57.78,48.9 57.47,48.9 56.52,49.85 56.52,51.44 P8.32
  LYR4 w0.133: v1(64.01,45.21) 64.77,44.45 67.31,44.45 67.84,44.98 67.84,45.82 65.91,47.75 58.93,47.75 v1(58.42,48.26)
  BOTTOM w0.121: v1(49.72,34.81) 49.72,39.43 C164.1 50.67,40.39 50.67,41.78 52.96,44.07 57.53,44.07 57.91,44.45 63.25,44.45 v1(64.01,45.21) ; v1(58.42,48.26) R80.1
LCD_DE: length 31.5
  TOP w0.121: v1(50.93,45.21) 50.93,43.05 49.66,41.78 49.66,41.4 R48.2 ; v1(61.09,34.8) 61.25,34.96 U11.20
  LYR4 w0.133: v1(50.93,45.21) 51.31,44.83 53.47,44.83 57.02,41.27 57.6,41.27 59.18,39.69 59.18,36.7 v1(61.09,34.8)
  BOTTOM w0.121: 55.24,52.7 53.98,51.44 53.98,49.78 51.05,46.86 51.05,45.97 50.93,45.85 v1(50.93,45.21)
LCD_HSYNC: length 28.4
  TOP w0.121: v1(62.36,34.8) 62.25,34.9 U11.22 ; R47.2 51.44,41.78 52.2,42.55 52.2,45.72 v1(52.7,46.23)
  LYR4 w0.133: v1(52.7,46.23) 53.59,46.23 57.09,42.74 58.23,42.74 60.2,40.77 60.2,36.96 v1(62.36,34.8)
  BOTTOM w0.121: v1(52.7,46.23) 52.7,47.62 55.24,50.16
LCD_PCLK: length 20.3
  TOP w0.121: R45.2 50.16,44.96 50.3,45.1 v1(50.32,45.1) 50.32,45.18 50.72,45.58 50.72,48.62 51.44,49.34 51.44,51.44 P8.28 ; v1(57.66,42.25) U11.4
  LYR4 w0.133: v1(50.32,45.1) 50.32,45.17 50.52,45.37 50.52,45.44 51.31,46.23 51.69,46.23 52.32,45.59 53.72,45.59 57.06,42.25 v1(57.66,42.25)
LCD_VSYNC: length 23.6
  TOP w0.121: U11.21 61.75,34.83 v1(61.72,34.8) ; R46.2 v1(51.44,45.72) 51.44,47.88 52.7,49.15 P8.27
  LYR4 w0.133: v1(61.72,34.8) 59.69,36.83 59.69,39.75 57.78,41.66 57.15,41.66 53.59,45.21 51.94,45.21 v1(51.44,45.72)
LCDDE: length 6.9
  TOP w0.121: v1(48.92,34.01) U5.R6 ; R48.1 v1(50.16,39.12)
  LYR3 w0.121: 49.32,35.18 49.32,34.41 v1(48.92,34.01)
  LYR3 w0.133: 49.32,35.18 49.53,35.39 49.53,38.48 v1(50.16,39.12)
LCDPCLK: length 8.1
  TOP w0.121: U5.V5 49.32,37.21 49.66,37.55 49.66,38.48 49.28,38.86 49.28,41.91 50.16,42.8 R45.1
LCDVHYNC: length 7.1
  TOP w0.121: v1(51.44,39.12) R47.1 ; v1(49.72,34.01) U5.R5
  LYR3 w0.121: 50.12,35.13 50.12,34.41 v1(49.72,34.01)
  LYR3 w0.133: v1(51.44,39.12) 51.44,36.45 50.12,35.13
LCDVSYNC: length 9.1
  TOP w0.121: R46.1 51.44,42.8 50.71,42.08 50.71,38.01 49.72,37.02 49.72,35.61 U5.U5
LDO_PGOOD: length 35.9
  TOP w0.121: v1(20.83,19.62) 21.46,18.99 U2.46 ; U5.B5 v1(49.72,22.81)
  LYR3 w0.133: v1(20.83,19.62) 21.53,20.32 25.91,20.32 27.05,21.46 33.53,21.46 34.9,20.09 37.57,20.09 38.86,18.8 43.18,18.8 43.81,19.43 48.64,19.43 49.72,20.51 v1(49.72,22.81)
LEDAA: length 1.8
  TOP w0.121: R72.2 D2.2
LEDAC: length 11.9
  TOP w0.121: Q1.6 12.37,47.83 11.68,48.51 2.86,48.51 2.35,48.01 D2.1
LEDBA: length 2.3
  TOP w0.121: R73.2 4.83,46.35 4,45.53 D3.2
LEDBC: length 17.6
  TOP w0.121: Q1.3 13.67,44.66 13.34,44.32 12.06,44.32 11.68,44.7 11.68,47.37 10.79,48.26 8.64,48.26 8.13,47.75 8.13,47.12 7.84,46.83 4.79,46.83 4.32,46.35 2.54,46.35 2.35,46.16 D3.1
LEDCA: length 3
  TOP w0.121: R74.2 5.21,45.4 4.95,45.15 4.95,44.58 4,43.62 D4.2
LEDCC: length 9.1
  TOP w0.121: Q2.6 8.62,47.11 8.26,46.74 8.26,46.23 7.91,45.88 5.24,45.88 4.7,45.34 4.7,44.7 4.45,44.45 2.54,44.45 2.35,44.26 D4.1
LEDDA: length 4
  TOP w0.121: D5.2 4.64,41.59 4.95,41.91 4.95,43.56 R71.2
LEDDC: length 11.8
  TOP w0.121: D5.1 2.35,42.35 2.54,42.55 4.45,42.55 4.7,42.8 4.7,43.81 5.21,44.32 5.21,44.77 5.37,44.93 7.91,44.93 8.51,44.32 9.78,44.32 10.17,44.72 Q2.3
MDIO_CLK: length 14.3
  TOP w0.121: U14.17 26.83,33.92 27.2,34.29 28.7,34.29 28.83,34.16 32,34.16 32.51,34.67 33.4,34.67 35.31,32.77 35.69,32.77 36.7,31.75 37.72,31.75 38.35,31.11 38.82,31.11 U5.M18
MDIO_DATA: length 15
  TOP w0.121: U14.16 27.89,32.87 28.17,33.15 28.83,33.15 29.34,33.66 R119.2 30.45,33.18 31.97,33.18 32.26,33.46 32.26,33.91 32.66,34.31 33.38,34.31 35.18,32.51 35.56,32.51 36.58,31.5 37.59,31.5 38.28,30.81 39.32,30.81 U5.M17
MII1_COL: length 24.2
  TOP w0.121: v1(40.12,27.61) U5.H16
  LYR3 w0.133: v1(40.12,27.61) 39.79,27.94 32.64,27.94 32.51,27.81 32.51,26.67 32.38,26.54 29.84,26.54 29.72,26.42 29.72,25.27 29.84,25.15 30.86,25.15 30.99,25.27 30.99,25.91 31.11,26.04 v1(31.75,26.04)
  BOTTOM w0.121: R138.1 31.43,32.26 31.84,32.26 32.15,31.95 32.15,30.84 32.51,30.48 32.51,26.8 v1(31.75,26.04)
MII1_CRS_DV: length 25.6
  TOP w0.121: v1(36.83,28.41) 39.32,28.41 U5.H17 ; R139.1 v1(31.75,32.7)
  BOTTOM w0.121: v1(36.83,28.41) 36.43,28.01 36.43,24.49 36.33,24.38 36.17,24.38 36.07,24.49 36.07,30.1 35.81,30.35 32.96,30.35 32.86,30.45 32.86,30.57 32.96,30.67 34.95,30.67 35.05,30.77 35.05,30.89 34.95,30.99 32.5,30.99 32.4,31.09 32.4,33.05 32.3,33.15 31.85,33.15 31.75,33.05 v1(31.75,32.7)
MII1_REFCLK: length 18
  TOP w0.121: R28.2 33.78,27.38 33.86,27.3 34.98,27.3 35.05,27.23 35.05,27 34.98,26.92 33.86,26.92 33.78,26.85 33.78,26.62 33.86,26.54 34.98,26.54 35.08,26.44 35.08,26.27 34.98,26.16 33.86,26.16 33.78,26.09 33.78,25.86 33.86,25.78 34.09,25.78 34.16,25.7 34.16,25.48 34.09,25.4 33.86,25.4 33.78,25.32 33.78,24.97 33.71,24.89 32.59,24.89 32.51,24.97 32.51,25.2 32.59,25.27 33.32,25.27 33.4,25.35 33.4,25.58 33.32,25.65 32.59,25.65 32.51,25.73 32.51,25.94 32.59,26.02 33.32,26.02 33.42,26.12 33.42,26.87 33.32,26.97 32.83,26.97 32.62,27.18 32.33,27.18 32.26,27.1 32.26,26.87 32.18,26.8 31.94,26.8 v1(31.75,26.99) R124.1
  BOTTOM w0.121: v1(31.75,26.99) 31.75,26.73 31.05,26.04 R140.1
MII1_RXCLK: length 23.8
  TOP w0.121: v1(31.75,30.8) 31.75,30.45 31.85,30.35 32.19,30.35 32.51,30.04 32.51,29.34 32.64,29.21 33.34,29.21 33.46,29.34 33.46,31.78 33.36,31.88 33.19,31.88 33.08,31.78 33.08,30.58 32.98,30.48 32.87,30.48 32.77,30.58 32.77,32.4 32.66,32.51 32.28,32.51 32.15,32.63 32.15,32.77 32.26,32.87 33.29,32.87 33.42,33 33.42,33.42 33.53,33.53 33.78,33.53 35.05,32.26 35.43,32.26 36.45,31.24 37.47,31.24 38.3,30.41 U5.L18
  BOTTOM w0.121: v1(31.75,30.8) 32.26,30.29 32.26,27.81 31.88,27.43 31.11,27.43 30.99,27.3 R131.1
MII1_RXD0: length 24.3
  TOP w0.121: v1(31.75,31.75) 31.75,31.56 R128.1 ; U5.M16 40.12,31.61 v1(39.32,31.61)
  LYR3 w0.133: v1(39.32,31.61) 38.91,32.02 32.64,32.02 32.36,32.3 31.37,32.3 31.24,32.42 31.24,33.02 31.37,33.15 32.28,33.15 32.38,33.25 32.38,34.06 32.28,34.16 31.37,34.16 31.24,34.29 31.24,34.92 31.37,35.05 32.28,35.05 32.38,35.15 32.38,35.97 32.28,36.07 30.96,36.07 30.86,35.97 30.86,31.85 30.96,31.75 v1(31.75,31.75)
MII1_RXD1: length 24.1
  TOP w0.121: U5.L15 v1(40.92,30.01) ; R127.1 v1(31.75,29.84)
  LYR3 w0.121: 39.75,29.61 40.52,29.61 v1(40.92,30.01)
  LYR3 w0.133: v1(31.75,29.84) 31.5,30.1 30.23,30.1 30.1,30.23 30.1,31.88 29.97,32 29.74,32 29.62,31.88 29.62,29.82 30.1,29.34 31.88,29.34 32.26,29.72 32.26,30.23 32.89,30.86 32.89,31.14 32.99,31.24 33.17,31.24 33.27,31.14 33.27,30.71 33.38,30.61 33.55,30.61 33.66,30.71 33.66,31.14 33.76,31.24 33.93,31.24 34.04,31.14 34.04,30.71 34.14,30.61 34.32,30.61 34.42,30.71 34.42,31.14 34.52,31.24 34.7,31.24 34.8,31.14 34.8,30.71 34.9,30.61 35.08,30.61 35.15,30.68 35.15,31.14 35.26,31.24 37.19,31.24 38.82,29.61 39.75,29.61
MII1_RXD2: length 24.1
  TOP w0.121: U5.L16 v1(40.92,30.81) ; R126.1 30.99,29.24 31.09,29.34 31.39,29.34 31.5,29.24 31.5,28.99 31.6,28.89 31.78,28.89 31.88,28.99 31.88,29.36 31.98,29.46 32.16,29.46 32.26,29.36 32.26,28.99 32.36,28.89 33.66,28.89 33.78,29.02 33.78,32.03 33.68,32.13 33.12,32.13 33.02,32.23 33.02,32.41 33.12,32.51 33.55,32.51 33.66,32.61 33.66,32.92 33.76,33.02 33.94,33.02 34.69,32.27 34.69,30.85 34.8,30.73 34.96,30.73 35.07,30.85 35.07,31.91 35.17,32.01 35.31,32.01 35.58,31.74 35.58,31.36 35.68,31.26 36.07,31.26 36.2,31.13 36.2,30.92 36.07,30.8 v1(35.56,30.8)
  BOTTOM w0.121: v1(40.92,30.81) U5.L16 39.95,30.41 39.37,29.83 39.37,29.59 39.12,29.34 37.14,29.34 36.45,30.03 36.45,30.61 36.26,30.8 v1(35.56,30.8)
MII1_RXD3: length 24.4
  TOP w0.121: R125.1 31.62,28.57 33.91,28.57 34.04,28.7 34.04,32.16 34.14,32.26 34.32,32.26 34.42,32.16 34.42,28.68 34.52,28.57 36.09,28.57 36.18,28.66 36.18,29.36 36.09,29.45 35.96,29.45 35.86,29.34 35.86,28.93 35.76,28.83 35.57,28.83 35.47,28.93 35.47,29.34 35.36,29.45 35.28,29.45 35.18,29.34 35.18,28.93 35.08,28.83 34.9,28.83 34.8,28.93 34.8,30.25 34.9,30.35 35.69,30.35 35.94,30.1 36.09,30.1 36.35,30.35 36.6,30.35 36.86,30.1 37.13,30.1 37.23,30.2 37.23,30.78 37.31,30.86 37.49,30.86 37.59,30.76 37.59,30.11 37.69,30.01 39.32,30.01 U5.L17
MII1_RXDV: length 25.8
  TOP w0.121: U5.J17 v1(40.12,29.21)
  LYR3 w0.133: v1(40.12,29.21) 38.73,29.21 37.59,30.35 32.89,30.35 32.61,30.07 32.61,29.69 32,29.08 29.84,29.08 29.59,29.34 24.77,29.34 21.58,32.52 19.86,32.52 v1(18.73,33.66)
  BOTTOM w0.121: v1(18.73,33.66) R129.1
MII1_RXERR: length 24.3
  TOP w0.121: U5.J15 v1(40.92,29.21) ; R133.1 31.5,32.26 32.29,32.26 32.39,32.16 32.39,30.51 33.02,29.88 v1(33.02,29.84)
  LYR3 w0.121: 39.86,28.81 40.52,28.81 v1(40.92,29.21)
  LYR3 w0.133: v1(33.02,29.84) 33.02,28.57 33.15,28.45 33.55,28.45 33.66,28.55 33.66,30 33.76,30.1 33.93,30.1 34.04,30 34.04,28.55 34.14,28.45 34.44,28.45 34.54,28.55 34.54,30 34.65,30.1 34.82,30.1 34.92,30 34.92,28.55 35.03,28.45 35.2,28.45 35.31,28.55 35.31,29.24 35.41,29.34 35.59,29.34 35.69,29.24 35.69,28.55 35.79,28.45 35.94,28.45 36.07,28.57 36.07,29.87 36.17,29.97 37.47,29.97 37.57,29.87 37.57,28.96 37.72,28.81 39.86,28.81
MII1_TXCLK: length 22.4
  TOP w0.121: U5.K18 37.47,29.61 37.23,29.84 v1(35.56,29.84)
  LYR5_PWR w0.121: v1(31.75,35.56) 32.51,34.8 33.4,34.8 36.07,32.13 36.07,30.35 v1(35.56,29.84)
  BOTTOM w0.121: v1(31.75,35.56) 32.26,35.56 32.38,35.68 32.38,36.58 32.26,36.7 27.69,36.7 27.58,36.6 27.58,36.43 27.69,36.32 30.67,36.32 30.99,36 R134.1
MII1_TXD0: length 28
  TOP w0.121: U5.K17 39.32,29.21 37.47,29.21 37.19,29.48 36.53,29.48 36.43,29.38 36.43,28.4 36.35,28.32 32.26,28.32 32.15,28.21 32.15,27.61 32,27.46 28.92,27.46 v1(28.45,27.94) ; R39.1 v1(19.67,35.94)
  LYR4 w0.133: v1(19.67,35.94) 20.95,35.94 22.35,34.54 22.35,31.62 25.53,28.45 27.94,28.45 v1(28.45,27.94)
MII1_TXD1: length 28
  TOP w0.121: v1(19.65,35.02) 19.68,35.05 R40.1 ; v1(40.12,30.01) U5.K16
  LYR3 w0.133: v1(40.12,30.01) 38.82,30.01 37.34,31.5 32.64,31.5 32.16,31.01 32.16,30.63 31.92,30.39 30.48,30.39 30.35,30.52 30.35,32.98 30.23,33.11 27.27,33.11 27.14,33.24 27.14,33.39 27,33.53 26.74,33.53 26.6,33.39 26.6,33.24 26.47,33.11 26.2,33.11 26.07,33.24 26.07,33.39 25.94,33.53 25.67,33.53 25.54,33.39 25.54,33.24 25.4,33.11 25.14,33.11 25,33.24 25,33.39 24.87,33.53 24.6,33.53 24.47,33.39 24.47,33.24 24.34,33.11 23.79,33.11 21.84,35.05 20.07,35.05 20.03,35.02 v1(19.65,35.02)
MII1_TXD2: length 28.2
  TOP w0.121: U5.K15 v1(41.72,30.01) ; R41.1 21.4,36.83 22.16,36.07 27.69,36.07 28.18,35.58 v1(28.57,35.58)
  LYR3 w0.121: 39.88,30.41 41.32,30.41 41.72,30.01 v1(41.72,30.01)
  LYR3 w0.133: v1(28.57,35.58) 28.57,36.32 28.71,36.45 30.48,36.45 30.61,36.32 30.61,31.37 30.71,31.27 32.03,31.27 32.51,31.75 37.59,31.75 38.93,30.41 39.88,30.41
MII1_TXD3: length 28
  TOP w0.121: v1(36.83,29.08) 36.83,29.06 37.08,28.81 U5.J18 ; R42.1 21.59,37.97 21.84,37.97 22.32,37.5 22.32,37.33 22,37 22,36.83 22.12,36.71 22.29,36.71 22.61,37.03 22.78,37.03 23.46,36.35 27.78,36.35 28.16,35.98 29.43,35.98 29.72,35.69 29.72,34.69 29.84,34.57 30.11,34.57 30.23,34.69 30.23,35.81 30.35,35.94 30.61,35.94 30.73,35.81 30.73,34.67 30.86,34.54 31.11,34.54 31.24,34.67 31.24,34.93 31.36,35.05 33.78,35.05 v1(35.56,33.27)
  LYR5_PWR w0.121: v1(35.56,33.27) 36.32,32.51 36.32,29.59 v1(36.83,29.08)
MII1_TXEN: length 28.4
  TOP w0.121: v1(24.49,34.54) 24.26,34.54 23.75,35.05 23.75,35.18 ; v1(40.12,28.41) U5.J16
  LYR3 w0.133: v1(40.12,28.41) 37.44,28.41 37.34,28.51 37.34,29.49 37.24,29.59 36.45,29.59 36.32,29.46 36.32,28.32 36.2,28.19 32.38,28.19 32.26,28.07 32.26,27.56 32.13,27.43 26.92,27.43 26.8,27.56 26.8,28.79 26.9,28.89 v1(28.45,28.89)
  LYR4 w0.133: v1(24.49,34.54) 24.9,34.54 26.92,32.52 26.92,30.42 v1(28.45,28.89)
MMC0_CD: length 73.7
  TOP w0.121: v1(40.92,23.61) U5.C15
  LYR4 w0.133: v1(60.96,12.45) 62.48,13.97 67.69,13.97 71.63,17.91 71.63,25.93 v1(73.46,27.77)
  BOTTOM w0.121: v1(40.92,23.61) 40.52,23.21 40.52,21.84 39.53,20.85 36.09,20.85 35.42,20.18 35.42,19.55 34.61,18.73 ; v1(73.46,27.77) 73.89,28.19 R157.1 74.3,28.7 75.44,29.84 78.87,29.84 79.43,30.41 P10.10 ; 34.61,18.73 P2.19 ; 34.61,18.73 35.31,18.03 35.31,16.26 36,15.56 40.07,15.56 40.89,14.73 40.89,14.22 41.96,13.16 46.91,13.16 47.09,13.34 60.07,13.34 v1(60.96,12.45)
MMC0_CLKO: length 10.6
  TOP w0.121: R16.1 31.49,24.26 31.88,23.87 32.92,23.87 32.92,23.87 33.08,23.87 35.24,26.04 37.08,26.04 38.66,27.61 39.32,27.61 U5.G17
MMC0_CMD: length 83.3
  TOP w0.121: U5.G18 38.64,27.21 37.21,25.78 35.34,25.78 33.18,23.62 33.02,23.62 32.38,22.99 v1(32.38,20.32)
  LYR3 w0.133: v1(72.01,36.07) 71.62,36.07 71.61,36.09 67.33,36.09 66.93,35.69 66.93,33.27 68.45,31.75 68.45,26.92 68.9,26.48 68.9,18.03 65.95,15.09 54.25,15.09 53.34,16 48.39,16 46.61,17.78 45.21,17.78 44.96,18.03 39.37,18.03 38.61,17.27 34.04,17.27 31.98,19.33 31.98,19.91 v1(32.38,20.32)
  BOTTOM w0.121: v1(72.01,36.07) 71.88,36.2 69.62,36.2 69.37,36.45 69.37,37.45 68.97,37.85 66.92,37.85 66.8,37.97 R15.1
MMC0_DAT0: length 66.3
  TOP w0.121: v1(40.12,26.81) U5.G16
  LYR3 w0.133: v1(39.88,16.51) 40.39,17.02 45.85,17.02 48.51,14.35 66.74,14.35 70.99,18.61 70.99,32.51 v1(68.71,34.8)
  LYR4 w0.133: v1(39.88,16.51) 38.35,18.03 38.35,18.46 38.35,18.47 38.35,21.47 38.1,21.72 38.1,22.23 38.35,22.48 38.35,22.49 38.36,22.5 38.36,25.25 39.92,26.81 v1(40.12,26.81)
  BOTTOM w0.121: R31.1 66.8,34.93 66.94,35.07 68.44,35.07 v1(68.71,34.8)
MMC0_DAT1: length 63.3
  TOP w0.121: v1(40.92,26.81) U5.G15
  LYR3 w0.133: v1(68.83,33.27) 70.61,31.49 70.61,18.73 66.48,14.61 53.47,14.61 52.58,15.49 47.88,15.49 46.1,17.27 v1(39.88,17.27)
  LYR4 w0.121: v1(40.92,26.81) 40.52,26.41 39.95,26.41 39.74,26.19
  LYR4 w0.133: v1(39.88,17.27) 38.58,18.57 38.58,20.86 38.93,21.21 38.93,25.39 39.74,26.19
  BOTTOM w0.121: v1(68.83,33.27) 68.46,33.27 68.34,33.15 66.92,33.15 66.8,33.27 R32.1
MMC0_DAT2: length 79
  TOP w0.121: U5.F18 38.22,26.41 37.34,25.53 35.44,25.53 33.28,23.37 33.15,23.37 32.64,22.86 32.64,21.34 33.42,20.56 33.42,19.83 33.15,19.56 v1(33.02,19.56)
  LYR3 w0.133: v1(69.6,41.27) 69.6,40.26 66.17,36.83 66.17,32.89 67.69,31.37 67.69,26.54 68.26,25.97 68.26,18.41 66.1,16.26 63.12,16.26 62.48,15.62 56.19,15.62 55.56,16.26 54.36,16.26 53.85,16.76 48.64,16.76 46.23,19.18 44.07,19.18 43.43,18.54 34.04,18.54 v1(33.02,19.56)
  BOTTOM w0.121: v1(69.6,41.27) 68.83,42.04 67.06,42.04 66.8,41.78 R2.1
MMC0_DAT3: length 85.7
  TOP w0.121: U5.F17 39.32,26.01 38.19,26.01 37.47,25.29 35.55,25.29 33.37,23.11 33.27,23.11 32.89,22.73 32.89,21.46 33.78,20.57 33.78,19.56 33.27,19.05 32.89,19.05 v1(32.38,19.56)
  LYR3 w0.133: v1(32.38,19.56) 34.42,17.53 38.35,17.53 39.12,18.29 43.69,18.29 44.32,18.92 45.97,18.92 48.64,16.26 53.72,16.26 54.61,15.37 62.74,15.37 63.37,16 66.36,16 68.58,18.22 68.58,26.16 68.07,26.67 68.07,31.5 66.55,33.02 66.55,36.7 68.96,39.12 v1(72.14,39.12)
  BOTTOM w0.121: v1(72.14,39.12) 71.75,39.5 69.6,39.5 69.47,39.62 68.33,39.62 68.2,39.75 67.31,39.75 R13.1
MMC1_CLK: length 49.8
  TOP w0.121: R35.2 C175.1 46.42,42.04 46.23,42.23 46.23,43.94 44.41,45.76 44.41,49.49 P8.21
  TOP w0.203: U13.M6 v2(28.09,42.66)
  LYR4 w0.133: v2(28.09,42.66) 28.84,42.66 29.08,42.42 29.08,41.02 29.21,40.89 29.46,40.89 29.59,41.02 29.59,42.8 29.72,42.93 29.97,42.93 30.1,42.79 30.1,41.03 30.23,40.89 30.47,40.89 30.61,41.03 30.61,42.93 31.11,43.43 31.11,44.73 31.62,45.24 35.21,45.24 37.85,47.88 38.69,47.88 38.82,48.01 38.82,48.76 38.95,48.9 39.22,48.9 39.35,48.76 39.35,48.01 39.49,47.88 39.75,47.88 39.89,48.01 39.89,48.76 40.02,48.9 40.29,48.9 40.42,48.76 40.42,48.01 40.55,47.88 40.89,47.88 41.02,48.01 41.02,48.77 41.15,48.9 41.4,48.9 41.53,48.77 41.53,47.87 41.65,47.75 43.31,47.75 43.43,47.88 43.43,49.15 43.56,49.28 43.81,49.28 43.94,49.15 43.94,48.51 44.07,48.39 44.26,48.39 44.41,48.53 44.41,49.49 P8.21
  BOTTOM w0.121: P8.21 R110.2
MMC1_CMD: length 39.2
  TOP w0.121: R36.2 45.97,41.66 45.85,41.78 45.85,43.81 44.07,45.59 44.07,49.28 43.81,49.53 43.81,51.44 P8.20
  TOP w0.203: U13.M5 v2(28.09,43.16)
  LYR4 w0.133: v2(28.09,43.16) 30.5,45.57 35.03,45.57 37.72,48.26 37.72,48.26 38.73,49.28 38.73,50.93 39.24,51.44 41.27,51.44 P8.20
  BOTTOM w0.121: R109.2 42.42,48.26 41.4,49.28 41.4,51.56 P8.20
MMC1_DAT0: length 37.3
  TOP w0.121: U13.A3 v2(33.34,43.91)
  LYR4 w0.133: P8.25 50.16,49.21 49.47,48.51 46.52,48.51 46.39,48.38 46.39,48.1 46.55,47.94 47.87,47.94 48.07,47.75 48.07,47.56 47.88,47.37 45.34,47.37 44.45,46.48 44.45,45.09 44.2,44.83 39.16,44.83 39.02,44.96 39.02,45.84 38.89,45.97 38.62,45.97 38.49,45.84 38.49,44.96 38.36,44.83 38.09,44.83 37.96,44.96 37.96,45.84 37.82,45.97 37.56,45.97 37.42,45.84 37.42,44.96 37.29,44.83 36.32,44.83 35.4,43.91 v2(33.34,43.91)
  BOTTOM w0.121: R43.2 R101.2 50.67,47.75 50.67,48.27 50.55,48.39 48.51,48.39 48.35,48.56 48.35,48.73 48.51,48.9 50.85,48.9 50.97,49.02 50.97,49.36 P8.25
MMC1_DAT1: length 33.7
  TOP w0.121: U13.A4 v2(33.34,43.41)
  LYR4 w0.133: P8.24 48.58,52.7 49.85,51.44 50.8,51.44 51.31,50.93 51.31,49.53 49.85,48.07 49.21,48.07 47.88,46.74 46.61,46.74 45.72,45.85 45.72,45.47 44.7,44.45 37.08,44.45 36.04,43.41 v2(33.34,43.41)
  BOTTOM w0.121: R44.2 R102.2 45.97,49.28 46.35,49.66 46.35,51.44 P8.24
MMC1_DAT2: length 15.2
  TOP w0.121: U13.A5 v2(32.84,43.41)
  LYR3 w0.133: v2(32.84,43.41) 27.74,48.51 26.42,48.51 P8.5
  BOTTOM w0.121: R168.2 R103.2 25.65,49.28 P8.5
MMC1_DAT3: length 19.8
  TOP w0.121: U13.B2 v2(32.34,44.41)
  LYR3 w0.133: P8.6 26.04,51.44 26.04,49.4 26.54,48.9 27.86,48.9 v2(32.34,44.41)
  BOTTOM w0.121: P8.6 26.04,51.44 26.04,49.78 27.43,48.39 R104.2 R169.2
MMC1_DAT4: length 29.2
  TOP w0.121: U13.B3 v2(32.85,44.41)
  LYR4 w0.133: v2(32.85,44.41) 33.27,44.83 35.31,44.83 37.34,46.86 37.8,46.86 37.93,47 37.93,47.36 38.06,47.5 38.33,47.5 38.46,47.36 38.46,47 38.6,46.86 38.86,46.86 39,47 39,47.36 39.13,47.5 39.4,47.5 39.53,47.36 39.53,47 39.66,46.86 39.93,46.86 40.06,47 40.06,47.36 40.2,47.5 40.46,47.5 40.6,47.36 40.6,47 40.73,46.86 41,46.86 41.13,47 41.13,47.36 41.26,47.5 41.53,47.5 41.66,47.36 41.66,47 41.8,46.86 42.06,46.86 42.2,47 42.2,47.24 42.33,47.37 42.6,47.37 42.73,47.24 42.73,47 42.86,46.86 43.37,46.86 46.23,49.72 46.23,50.79 46.36,50.93 46.86,50.93 P8.23
  BOTTOM w0.121: R170.2 R105.2 47.75,48.29 47.63,48.42 46.6,48.42 46.48,48.54 46.48,48.78 46.6,48.9 47.63,48.9 47.75,49.02 47.75,50.04 P8.23
MMC1_DAT5: length 37.4
  TOP w0.121: U13.B4 v2(32.85,43.91)
  LYR4 w0.133: P8.22 46.35,51.44 48.77,51.44 49.02,51.18 49.02,49.41 48.76,49.15 46.48,49.15 43.69,46.35 43.69,45.34 43.56,45.21 43.31,45.21 43.18,45.34 43.18,46.35 43.05,46.48 41.66,46.48 41.53,46.35 41.53,45.47 41.27,45.21 40.51,45.21 40.26,45.47 40.26,46.35 40.13,46.48 37.47,46.48 35.31,44.32 33.26,44.32 v2(32.85,43.91)
  BOTTOM w0.121: P8.22 43.81,51.44 43.81,49.66 44.2,49.28 44.2,49.03 44.08,48.91 43.17,48.91 43.05,48.79 43.05,48.26 43.31,48.01 R106.2 R171.2
MMC1_DAT6: length 17.1
  TOP w0.121: U13.B5 v2(32.35,43.41)
  LYR3 w0.133: P8.3 23.24,49.15 25.27,49.15 26.29,48.13 27.62,48.13 v2(32.35,43.41)
  BOTTOM w0.121: P8.3 22.23,49.02 22.99,48.26 R107.2 R172.2
MMC1_DAT7: length 25.1
  TOP w0.121: U13.B6 v2(32.35,42.91)
  LYR3 w0.133: v2(32.35,42.91) 27.5,47.75 26.16,47.75 25.14,48.77 21.97,48.77 21.08,49.66 21.08,51.56 P8.4
  BOTTOM w0.121: R173.2 R108.2 24.77,48.39 23.5,49.66 23.5,51.44 P8.4
MODE2: length 3.9
  TOP w0.121: U14.15 28.11,32.37 v1(28.45,32.7)
  BOTTOM w0.121: R138.2 R113.1 29.4,33.66 v1(28.45,32.7)
OSC0_IN: length 6.8
  TOP w0.121: v1(45.72,38.1) 45.32,37.7 U5.V10
  BOTTOM w0.121: Y2.2 46.86,41.15 C25.1 R17.1 v1(45.72,38.1)
OSC0_OUT: length 7.7
  TOP w0.121: v1(44.92,38.1) 44.92,35.61 U5.U11
  BOTTOM w0.121: v1(44.92,38.1) 44.7,38.32 R17.2 C26.1 43.56,41.15 Y2.1
OSC1_IN: length 8.1
  TOP w0.121: Y1.1 49.93,16.72 50.16,16.95 v1(50.16,17.78) 50.16,18.67 49.66,19.18 49.66,21.27 U5.A6
  BOTTOM w0.121: v1(50.16,17.78) 50.48,17.46 C21.2
OSC1_OUT: length 8.2
  TOP w0.121: U5.A4 50.12,21.89 50.36,21.65 50.36,19.49 v1(52.07,17.78) 52.07,16.95 52.31,16.72 Y1.4
  BOTTOM w0.121: C22.2 51.75,17.46 v1(52.07,17.78)
P_BYPASS: length 2.8
  TOP w0.121: U2.47 21.06,18.88 20.83,19.11 v1(20,19.11)
  BOTTOM w0.121: C4.2 v1(20,19.11)
P_INT_LDO: length 4.4
  TOP w0.121: U2.48 19.85,18.31 18.8,19.37 C3.2
P_L1: length 4.6
  TOP w0.203: U2.20 23.46,11.18
  BOTTOM w0.381: v1(22.99,9.91) 22.99,8.89 L1.1 22.35,8.89 v1(22.35,9.91) v1(22.99,9.91)
P_L2: length 4.5
  TOP w0.203: 24.66,11.53 U2.23
  BOTTOM w0.381: 25.15,9.21 L2.1 24.38,8.7 24.38,9.78 24.51,9.91 v1(24.64,9.91) v1(25.27,9.91) 25.15,9.78 25.15,9.21
P_L3: length 2.9
  BOTTOM w0.381: 28.57,16.7 L3.1 29.21,16.7 v1(29.21,17.4) v1(28.57,17.4) 28.57,16.7
PHY_VDDCR: length 4.1
  TOP w0.254: U14.6 25.83,28.06 26.21,27.69 v1(26.23,27.69)
  BOTTOM w0.381: v1(26.23,27.69) 26.93,27.69 27.18,27.93 C134.1 C136.1
PHY_XTAL1: length 4.7
  TOP w0.121: v1(28.26,25.4) 27.3,25.4 Y3.1
  BOTTOM w0.121: v1(28.26,25.4) 27.18,25.4 C143.1 R142.1 R141.2
PHY_XTAL2: length 3.4
  TOP w0.121: U14.4 24.83,27.94 24.9,27.87 24.9,27.17 v1(25.08,26.99)
  BOTTOM w0.121: R143.1 R141.1 v1(25.08,26.99)
PHYX: length 3.7
  TOP w0.121: v1(21.91,25.4) 22.87,25.4 Y3.2
  BOTTOM w0.121: v1(21.91,25.4) 22.99,25.4 C142.1 R143.2
PMIC_INT: length 24.3
  TOP w0.121: v1(21.59,19.62) 21.86,19.35 U2.45 ; U5.B18 37.59,21.88 37.59,20.7 36.96,20.07 v1(36.96,19.68)
  LYR3 w0.133: v1(21.59,19.62) 22.03,20.07 29.72,20.07 30.48,20.83 33.15,20.83 34.8,19.18 36.45,19.18 v1(36.96,19.68)
  BOTTOM w0.121: v1(21.59,19.62) R1.2
PMIC_PGOOD: length 35
  TOP w0.121: v1(26.92,12.76) 26.56,13.13 26.56,13.23 26.35,13.44 U2.26 ; v1(40.92,22.81) U5.B15 ; v1(30.23,9.14) 30.48,8.89 31.59,8.89 31.75,9.05 U16.2
  LYR3 w0.121: 39.95,23.21 40.52,23.21 v1(40.92,22.81)
  LYR3 w0.133: 39.95,23.21 38.1,23.21 37.62,22.73 35.69,22.73 34.8,23.62 32.26,23.62 32,23.88 29.72,23.88 v1(29.21,24.38) ; v1(26.92,12.76) 27.75,12.76 28.7,11.81 28.7,10.67 v1(30.23,9.14)
  LYR4 w0.133: v1(29.21,24.38) 28.07,23.24 28.07,13.91 v1(26.92,12.76)
